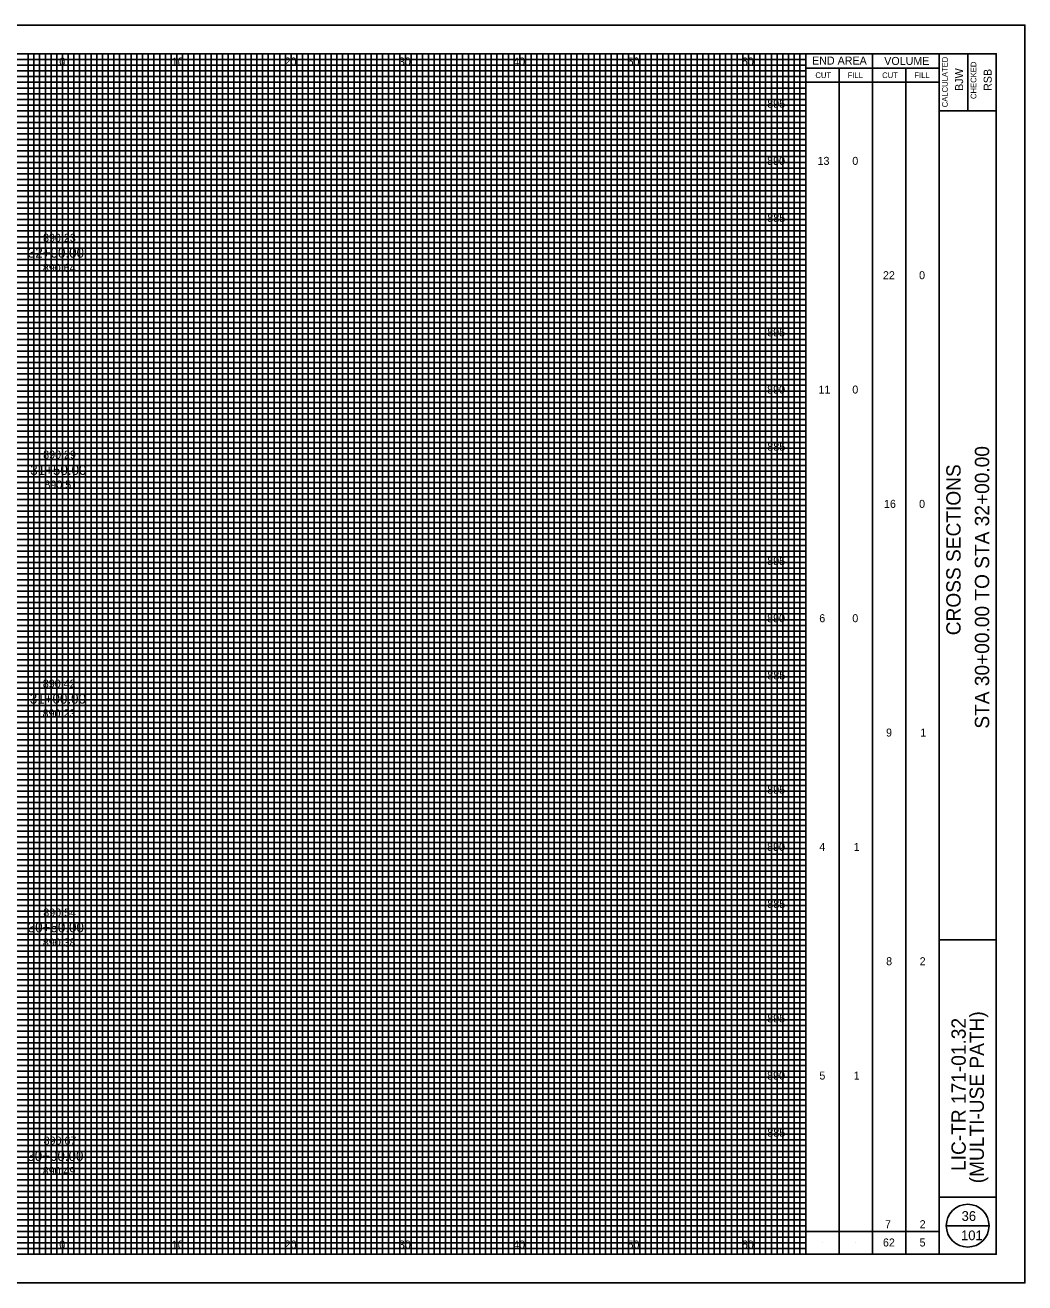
# Model space of a CAD drawing. Extents: x -10 to 160, y -2 to 2522.
# Drawn here: x 72.6 to 160, y 917.5 to 1027.5 of the extents above; entities that cross this region are included whole.
import ezdxf

# ---------------------------------------------------------------- set-up
doc = ezdxf.new("R2010")
doc.units = 0
for name, color, linetype in [('GK_Cells', 7, 'Continuous'), ('GK_Patterns', 7, 'Continuous'), ('TX_P_10', 7, 'Continuous'), ('TX_X_10', 7, 'Continuous'), ('XS_P_Finished_Grade_Seeded', 7, 'Continuous'), ('XS_P_Pavt_Surface', 7, 'Continuous'), ('XS_P_Subgrade', 7, 'Continuous'), ('XS_X_Ground_Line', 7, 'Continuous')]:
    doc.layers.add(name, color=color, linetype=linetype)

msp = doc.modelspace()

# ---------------------------------------------------------------- linework, layer by layer
at = {"layer": 'GK_Cells'}
msp.add_lwpolyline([(-10, 917.5), (160, 917.5), (160, 1027.5), (-10, 1027.5)], close=True, dxfattribs=at)
at = {"layer": 'TX_P_10'}
for p, q in [((140.83, 920), (140.83, 1025)), ((146.67, 920), (146.67, 1025)), ((140.83, 1023.75), (152.5, 1023.75)), ((143.75, 920), (143.75, 1023.75)), ((149.58, 920), (149.58, 1023.75)), ((140.83, 1022.5), (152.5, 1022.5)), ((140.83, 922), (152.5, 922)), ((153.12, 922.5), (156.88, 922.5)), ((142.29, 921), (142.29, 921)), ((145.21, 921), (145.21, 921)), ((148.12, 921), (148.12, 921)), ((151.04, 921), (151.04, 921))]:
    msp.add_line(p, q, dxfattribs=at)
msp.add_circle((155, 922.5), 1.87, dxfattribs=at)
at = {"layer": 'TX_X_10'}
for p, q in [((75.83, 920), (75.83, 1025)), ((80.83, 920), (80.83, 1025)), ((85.83, 920), (85.83, 1025)), ((90.83, 920), (90.83, 1025)), ((95.83, 920), (95.83, 1025)), ((100.83, 920), (100.83, 1025)), ((105.83, 920), (105.83, 1025)), ((110.83, 920), (110.83, 1025)), ((115.83, 920), (115.83, 1025)), ((120.83, 920), (120.83, 1025)), ((125.83, 920), (125.83, 1025)), ((130.83, 920), (130.83, 1025)), ((135.83, 920), (135.83, 1025)), ((5.83, 1020), (140.83, 1020)), ((5.83, 1015), (140.83, 1015)), ((5.83, 1010), (140.83, 1010)), ((5.83, 1005), (140.83, 1005)), ((5.83, 1000), (140.83, 1000)), ((5.83, 995), (140.83, 995)), ((5.83, 990), (140.83, 990)), ((5.83, 985), (140.83, 985)), ((5.83, 980), (140.83, 980)), ((5.83, 975), (140.83, 975)), ((5.83, 970), (140.83, 970)), ((5.83, 965), (140.83, 965)), ((5.83, 960), (140.83, 960)), ((5.83, 955), (140.83, 955)), ((5.83, 950), (140.83, 950)), ((5.83, 945), (140.83, 945)), ((5.83, 940), (140.83, 940)), ((5.83, 935), (140.83, 935)), ((5.83, 930), (140.83, 930)), ((5.83, 925), (140.83, 925))]:
    msp.add_line(p, q, dxfattribs=at)
at = {"layer": 'XS_P_Pavt_Surface'}
for p, q in [((152.5, 920), (152.5, 1025)), ((155, 1025), (155, 1020)), ((152.5, 1020), (157.5, 1020)), ((152.5, 947.5), (157.5, 947.5)), ((152.5, 925), (157.5, 925))]:
    msp.add_line(p, q, dxfattribs=at)
msp.add_lwpolyline([(0, 1025), (157.5, 1025), (157.5, 920), (0, 920)], close=True, dxfattribs=at)
at = {"layer": 'XS_X_Ground_Line'}
for p, q in [((5.83, 1024.5), (140.83, 1024.5)), ((72.83, 920), (72.83, 1025)), ((73.33, 920), (73.33, 1025)), ((73.83, 920), (73.83, 1025)), ((74.33, 920), (74.33, 1025)), ((74.83, 920), (74.83, 1025)), ((75.33, 920), (75.33, 1025)), ((76.33, 920), (76.33, 1025)), ((76.83, 920), (76.83, 1025)), ((77.33, 920), (77.33, 1025)), ((77.83, 920), (77.83, 1025)), ((78.33, 920), (78.33, 1025)), ((78.83, 920), (78.83, 1025)), ((79.33, 920), (79.33, 1025)), ((79.83, 920), (79.83, 1025)), ((80.33, 920), (80.33, 1025)), ((81.33, 920), (81.33, 1025)), ((81.83, 920), (81.83, 1025)), ((82.33, 920), (82.33, 1025)), ((82.83, 920), (82.83, 1025)), ((83.33, 920), (83.33, 1025)), ((83.83, 920), (83.83, 1025)), ((84.33, 920), (84.33, 1025)), ((84.83, 920), (84.83, 1025)), ((85.33, 920), (85.33, 1025)), ((86.33, 920), (86.33, 1025)), ((86.83, 920), (86.83, 1025)), ((87.33, 920), (87.33, 1025)), ((87.83, 920), (87.83, 1025)), ((88.33, 920), (88.33, 1025)), ((88.83, 920), (88.83, 1025)), ((89.33, 920), (89.33, 1025)), ((89.83, 920), (89.83, 1025)), ((90.33, 920), (90.33, 1025)), ((91.33, 920), (91.33, 1025)), ((91.83, 920), (91.83, 1025)), ((92.33, 920), (92.33, 1025)), ((92.83, 920), (92.83, 1025)), ((93.33, 920), (93.33, 1025)), ((93.83, 920), (93.83, 1025)), ((94.33, 920), (94.33, 1025)), ((94.83, 920), (94.83, 1025)), ((95.33, 920), (95.33, 1025)), ((96.33, 920), (96.33, 1025)), ((96.83, 920), (96.83, 1025)), ((97.33, 920), (97.33, 1025)), ((97.83, 920), (97.83, 1025)), ((98.33, 920), (98.33, 1025)), ((98.83, 920), (98.83, 1025)), ((99.33, 920), (99.33, 1025)), ((99.83, 920), (99.83, 1025)), ((100.33, 920), (100.33, 1025)), ((101.33, 920), (101.33, 1025)), ((101.83, 920), (101.83, 1025)), ((102.33, 920), (102.33, 1025)), ((102.83, 920), (102.83, 1025)), ((103.33, 920), (103.33, 1025)), ((103.83, 920), (103.83, 1025)), ((104.33, 920), (104.33, 1025)), ((104.83, 920), (104.83, 1025)), ((105.33, 920), (105.33, 1025)), ((106.33, 920), (106.33, 1025)), ((106.83, 920), (106.83, 1025)), ((107.33, 920), (107.33, 1025)), ((107.83, 920), (107.83, 1025)), ((108.33, 920), (108.33, 1025)), ((108.83, 920), (108.83, 1025)), ((109.33, 920), (109.33, 1025)), ((109.83, 920), (109.83, 1025)), ((110.33, 920), (110.33, 1025)), ((111.33, 920), (111.33, 1025)), ((111.83, 920), (111.83, 1025)), ((112.33, 920), (112.33, 1025)), ((112.83, 920), (112.83, 1025)), ((113.33, 920), (113.33, 1025)), ((113.83, 920), (113.83, 1025)), ((114.33, 920), (114.33, 1025)), ((114.83, 920), (114.83, 1025)), ((115.33, 920), (115.33, 1025)), ((116.33, 920), (116.33, 1025)), ((116.83, 920), (116.83, 1025)), ((117.33, 920), (117.33, 1025)), ((117.83, 920), (117.83, 1025)), ((118.33, 920), (118.33, 1025)), ((118.83, 920), (118.83, 1025)), ((119.33, 920), (119.33, 1025)), ((119.83, 920), (119.83, 1025)), ((120.33, 920), (120.33, 1025)), ((121.33, 920), (121.33, 1025)), ((121.83, 920), (121.83, 1025)), ((122.33, 920), (122.33, 1025)), ((122.83, 920), (122.83, 1025)), ((123.33, 920), (123.33, 1025)), ((123.83, 920), (123.83, 1025)), ((124.33, 920), (124.33, 1025)), ((124.83, 920), (124.83, 1025)), ((125.33, 920), (125.33, 1025)), ((126.33, 920), (126.33, 1025)), ((126.83, 920), (126.83, 1025)), ((127.33, 920), (127.33, 1025)), ((127.83, 920), (127.83, 1025)), ((128.33, 920), (128.33, 1025)), ((128.83, 920), (128.83, 1025)), ((129.33, 920), (129.33, 1025)), ((129.83, 920), (129.83, 1025)), ((130.33, 920), (130.33, 1025)), ((131.33, 920), (131.33, 1025)), ((131.83, 920), (131.83, 1025)), ((132.33, 920), (132.33, 1025)), ((132.83, 920), (132.83, 1025)), ((133.33, 920), (133.33, 1025)), ((133.83, 920), (133.83, 1025)), ((134.33, 920), (134.33, 1025)), ((134.83, 920), (134.83, 1025)), ((135.33, 920), (135.33, 1025)), ((136.33, 920), (136.33, 1025)), ((136.83, 920), (136.83, 1025)), ((137.33, 920), (137.33, 1025)), ((137.83, 920), (137.83, 1025)), ((138.33, 920), (138.33, 1025)), ((138.83, 920), (138.83, 1025)), ((139.33, 920), (139.33, 1025)), ((139.83, 920), (139.83, 1025)), ((140.33, 920), (140.33, 1025)), ((5.83, 1024), (140.83, 1024)), ((5.83, 1023.5), (140.83, 1023.5)), ((5.83, 1023), (140.83, 1023)), ((5.83, 1022.5), (140.83, 1022.5)), ((5.83, 1022), (140.83, 1022)), ((5.83, 1021.5), (140.83, 1021.5)), ((5.83, 1021), (140.83, 1021)), ((5.83, 1020.5), (140.83, 1020.5)), ((5.83, 1019.5), (140.83, 1019.5)), ((5.83, 1019), (140.83, 1019)), ((5.83, 1018.5), (140.83, 1018.5)), ((5.83, 1018), (140.83, 1018)), ((5.83, 1017.5), (140.83, 1017.5)), ((5.83, 1017), (140.83, 1017)), ((5.83, 1016.5), (140.83, 1016.5)), ((5.83, 1016), (140.83, 1016)), ((5.83, 1015.5), (140.83, 1015.5)), ((5.83, 1014.5), (140.83, 1014.5)), ((5.83, 1014), (140.83, 1014)), ((5.83, 1013.5), (140.83, 1013.5)), ((5.83, 1013), (140.83, 1013)), ((5.83, 1012.5), (140.83, 1012.5)), ((5.83, 1012), (140.83, 1012)), ((5.83, 1011.5), (140.83, 1011.5)), ((5.83, 1011), (140.83, 1011)), ((5.83, 1010.5), (140.83, 1010.5)), ((5.83, 1009.5), (140.83, 1009.5)), ((5.83, 1009), (140.83, 1009)), ((5.83, 1008.5), (140.83, 1008.5)), ((5.83, 1008), (140.83, 1008)), ((5.83, 1007.5), (140.83, 1007.5)), ((5.83, 1007), (140.83, 1007)), ((5.83, 1006.5), (140.83, 1006.5)), ((5.83, 1006), (140.83, 1006)), ((5.83, 1005.5), (140.83, 1005.5)), ((5.83, 1004.5), (140.83, 1004.5)), ((5.83, 1004), (140.83, 1004)), ((5.83, 1003.5), (140.83, 1003.5)), ((5.83, 1003), (140.83, 1003)), ((5.83, 1002.5), (140.83, 1002.5)), ((5.83, 1002), (140.83, 1002)), ((5.83, 1001.5), (140.83, 1001.5)), ((5.83, 1001), (140.83, 1001)), ((5.83, 1000.5), (140.83, 1000.5)), ((5.83, 999.5), (140.83, 999.5)), ((5.83, 999), (140.83, 999)), ((5.83, 998.5), (140.83, 998.5)), ((5.83, 998), (140.83, 998)), ((5.83, 997.5), (140.83, 997.5)), ((5.83, 997), (140.83, 997)), ((5.83, 996.5), (140.83, 996.5)), ((5.83, 996), (140.83, 996)), ((5.83, 995.5), (140.83, 995.5)), ((5.83, 994.5), (140.83, 994.5)), ((5.83, 994), (140.83, 994)), ((5.83, 993.5), (140.83, 993.5)), ((5.83, 993), (140.83, 993)), ((5.83, 992.5), (140.83, 992.5)), ((5.83, 992), (140.83, 992)), ((5.83, 991.5), (140.83, 991.5)), ((5.83, 991), (140.83, 991)), ((5.83, 990.5), (140.83, 990.5)), ((5.83, 989.5), (140.83, 989.5)), ((5.83, 989), (140.83, 989)), ((5.83, 988.5), (140.83, 988.5)), ((5.83, 988), (140.83, 988)), ((5.83, 987.5), (140.83, 987.5)), ((5.83, 987), (140.83, 987)), ((5.83, 986.5), (140.83, 986.5)), ((5.83, 986), (140.83, 986)), ((5.83, 985.5), (140.83, 985.5)), ((5.83, 984.5), (140.83, 984.5)), ((5.83, 984), (140.83, 984)), ((5.83, 983.5), (140.83, 983.5)), ((5.83, 983), (140.83, 983)), ((5.83, 982.5), (140.83, 982.5)), ((5.83, 982), (140.83, 982)), ((5.83, 981.5), (140.83, 981.5)), ((5.83, 981), (140.83, 981)), ((5.83, 980.5), (140.83, 980.5)), ((5.83, 979.5), (140.83, 979.5)), ((5.83, 979), (140.83, 979)), ((5.83, 978.5), (140.83, 978.5)), ((5.83, 978), (140.83, 978)), ((5.83, 977.5), (140.83, 977.5)), ((5.83, 977), (140.83, 977)), ((5.83, 976.5), (140.83, 976.5)), ((5.83, 976), (140.83, 976)), ((5.83, 975.5), (140.83, 975.5)), ((5.83, 974.5), (140.83, 974.5)), ((5.83, 974), (140.83, 974)), ((5.83, 973.5), (140.83, 973.5)), ((5.83, 973), (140.83, 973)), ((5.83, 972.5), (140.83, 972.5)), ((5.83, 972), (140.83, 972)), ((5.83, 971.5), (140.83, 971.5)), ((5.83, 971), (140.83, 971)), ((5.83, 970.5), (140.83, 970.5)), ((5.83, 969.5), (140.83, 969.5)), ((5.83, 969), (140.83, 969)), ((5.83, 968.5), (140.83, 968.5)), ((5.83, 968), (140.83, 968)), ((5.83, 967.5), (140.83, 967.5)), ((5.83, 967), (140.83, 967)), ((5.83, 966.5), (140.83, 966.5)), ((5.83, 966), (140.83, 966)), ((5.83, 965.5), (140.83, 965.5)), ((5.83, 964.5), (140.83, 964.5)), ((5.83, 964), (140.83, 964)), ((5.83, 963.5), (140.83, 963.5)), ((5.83, 963), (140.83, 963)), ((5.83, 962.5), (140.83, 962.5)), ((5.83, 962), (140.83, 962)), ((5.83, 961.5), (140.83, 961.5)), ((5.83, 961), (140.83, 961)), ((5.83, 960.5), (140.83, 960.5)), ((5.83, 959.5), (140.83, 959.5)), ((5.83, 959), (140.83, 959)), ((5.83, 958.5), (140.83, 958.5)), ((5.83, 958), (140.83, 958)), ((5.83, 957.5), (140.83, 957.5)), ((5.83, 957), (140.83, 957)), ((5.83, 956.5), (140.83, 956.5)), ((5.83, 956), (140.83, 956)), ((5.83, 955.5), (140.83, 955.5)), ((5.83, 954.5), (140.83, 954.5)), ((5.83, 954), (140.83, 954)), ((5.83, 953.5), (140.83, 953.5)), ((5.83, 953), (140.83, 953)), ((5.83, 952.5), (140.83, 952.5)), ((5.83, 952), (140.83, 952)), ((5.83, 951.5), (140.83, 951.5)), ((5.83, 951), (140.83, 951)), ((5.83, 950.5), (140.83, 950.5)), ((5.83, 949.5), (140.83, 949.5)), ((5.83, 949), (140.83, 949)), ((5.83, 948.5), (140.83, 948.5)), ((5.83, 948), (140.83, 948)), ((5.83, 947.5), (140.83, 947.5)), ((5.83, 947), (140.83, 947)), ((5.83, 946.5), (140.83, 946.5)), ((5.83, 946), (140.83, 946)), ((5.83, 945.5), (140.83, 945.5)), ((5.83, 944.5), (140.83, 944.5)), ((5.83, 944), (140.83, 944)), ((5.83, 943.5), (140.83, 943.5)), ((5.83, 943), (140.83, 943)), ((5.83, 942.5), (140.83, 942.5)), ((5.83, 942), (140.83, 942)), ((5.83, 941.5), (140.83, 941.5)), ((5.83, 941), (140.83, 941)), ((5.83, 940.5), (140.83, 940.5)), ((5.83, 939.5), (140.83, 939.5)), ((5.83, 939), (140.83, 939)), ((5.83, 938.5), (140.83, 938.5)), ((5.83, 938), (140.83, 938)), ((5.83, 937.5), (140.83, 937.5)), ((5.83, 937), (140.83, 937)), ((5.83, 936.5), (140.83, 936.5)), ((5.83, 936), (140.83, 936)), ((5.83, 935.5), (140.83, 935.5)), ((5.83, 934.5), (140.83, 934.5)), ((5.83, 934), (140.83, 934)), ((5.83, 933.5), (140.83, 933.5)), ((5.83, 933), (140.83, 933)), ((5.83, 932.5), (140.83, 932.5)), ((5.83, 932), (140.83, 932)), ((5.83, 931.5), (140.83, 931.5)), ((5.83, 931), (140.83, 931)), ((5.83, 930.5), (140.83, 930.5)), ((5.83, 929.5), (140.83, 929.5)), ((5.83, 929), (140.83, 929)), ((5.83, 928.5), (140.83, 928.5)), ((5.83, 928), (140.83, 928)), ((5.83, 927.5), (140.83, 927.5)), ((5.83, 927), (140.83, 927)), ((5.83, 926.5), (140.83, 926.5)), ((5.83, 926), (140.83, 926)), ((5.83, 925.5), (140.83, 925.5)), ((5.83, 924.5), (140.83, 924.5)), ((5.83, 924), (140.83, 924)), ((5.83, 923.5), (140.83, 923.5)), ((5.83, 923), (140.83, 923)), ((5.83, 922.5), (140.83, 922.5)), ((5.83, 922), (140.83, 922)), ((5.83, 921.5), (140.83, 921.5)), ((5.83, 921), (140.83, 921)), ((5.83, 920.5), (140.83, 920.5))]:
    msp.add_line(p, q, dxfattribs=at)

# ---------------------------------------------------------------- texts
at = {"layer": 'GK_Patterns'}
for s, height, p in [('0', 0.7, (75.55, 1023.97)), ('0', 0.7, (75.55, 1023.97)), ('10', 0.7, (85.39, 1023.97)), ('20', 0.7, (95.26, 1023.97)), ('30', 0.7, (105.25, 1023.97)), ('40', 0.7, (115.25, 1023.97)), ('50', 0.7, (125.25, 1023.97)), ('60', 0.7, (135.25, 1023.97)), ('895', 0.7, (137.47, 1020.28)), ('890', 0.7, (137.46, 1015.28)), ('13', 0.7, (141.87, 1015.28)), ('0', 0.7, (144.91, 1015.28)), ('885', 0.7, (137.48, 1010.28)), ('32+00.00', 0.875, (72.8, 1007.16)), ('22', 0.7, (147.59, 1005.28)), ('0', 0.7, (150.75, 1005.28)), ('895', 0.7, (137.47, 1000.28)), ('890', 0.7, (137.46, 995.28)), ('11', 0.7, (141.95, 995.28)), ('0', 0.7, (144.91, 995.28)), ('885', 0.7, (137.48, 990.28)), ('31+50.00', 0.875, (73.01, 988.16)), ('16', 0.7, (147.68, 985.28)), ('0', 0.7, (150.75, 985.28)), ('895', 0.7, (137.47, 980.28)), ('890', 0.7, (137.46, 975.28)), ('6', 0.7, (142.02, 975.28)), ('0', 0.7, (144.91, 975.28)), ('885', 0.7, (137.48, 970.28)), ('31+00.00', 0.875, (72.97, 968.16)), ('9', 0.7, (147.86, 965.28)), ('1', 0.7, (150.86, 965.28)), ('895', 0.7, (137.47, 960.28)), ('890', 0.7, (137.46, 955.28)), ('4', 0.7, (142.02, 955.28)), ('1', 0.7, (145.03, 955.28)), ('885', 0.7, (137.48, 950.28)), ('30+50.00', 0.875, (72.79, 948.16)), ('8', 0.7, (147.87, 945.28)), ('2', 0.7, (150.8, 945.28)), ('895', 0.7, (137.47, 940.28)), ('890', 0.7, (137.46, 935.28)), ('5', 0.7, (142.03, 935.28)), ('1', 0.7, (145.03, 935.28)), ('885', 0.7, (137.48, 930.28)), ('30+00.00', 0.875, (72.75, 928.16)), ('7', 0.7, (147.77, 922.28)), ('2', 0.7, (150.8, 922.28)), ('0', 0.7, (75.55, 920.5)), ('0', 0.7, (75.55, 920.5)), ('10', 0.7, (85.39, 920.5)), ('20', 0.7, (95.26, 920.5)), ('30', 0.7, (105.25, 920.5)), ('40', 0.7, (115.25, 920.5)), ('50', 0.7, (125.25, 920.5)), ('60', 0.7, (135.25, 920.5)), ('62', 0.7, (147.59, 920.68)), ('5', 0.7, (150.79, 920.68))]:
    msp.add_text(s, height=height, dxfattribs=at).set_placement(p)
at = {"layer": 'TX_P_10'}
for s, height, p in [('END AREA', 0.7, (141.39, 1024.05)), ('VOLUME', 0.7, (147.7, 1024.02)), ('CUT', 0.5, (141.68, 1022.87)), ('FILL', 0.5, (144.5, 1022.87)), ('CUT', 0.5, (147.52, 1022.87)), ('FILL', 0.5, (150.34, 1022.87)), ('36', 0.85, (154.47, 922.92)), ('101', 0.85, (154.42, 921.23))]:
    msp.add_text(s, height=height, dxfattribs=at).set_placement(p)
for s, height, p in [('CALCULATED', 0.5, (153.26, 1020.32)), ('CHECKED', 0.5, (155.76, 1021.04)), ('BJW', 0.7, (154.6, 1021.75)), ('RSB', 0.7, (157.1, 1021.75)), ('STA 30+00.00 TO STA 32+00.00', 1.25, (156.88, 965.97)), ('CROSS SECTIONS', 1.25, (154.38, 974.14)), ('LIC-TR 171-01.32', 1.25, (154.83, 927.29)), ('(MULTI-USE PATH)', 1.25, (156.42, 926.21))]:
    msp.add_text(s, height=height, rotation=90, dxfattribs=at).set_placement(p)
at = {"layer": 'XS_P_Finished_Grade_Seeded'}
for s, p in [('890.64', (74.11, 1005.92)), ('890.51', (74.25, 986.97)), ('890.23', (74.09, 966.95)), ('890.38', (74.11, 946.92)), ('890.49', (74.1, 926.93))]:
    msp.add_text(s, height=0.7, dxfattribs=at).set_placement(p)
at = {"layer": 'XS_P_Subgrade'}
for s, p in [('890.23', (74.13, 1008.55)), ('890.29', (74.14, 989.59)), ('890.42', (74.11, 969.56)), ('890.54', (74.15, 949.54)), ('890.67', (74.18, 929.59))]:
    msp.add_text(s, height=0.7, dxfattribs=at).set_placement(p)

doc.saveas('drawing.dxf')
